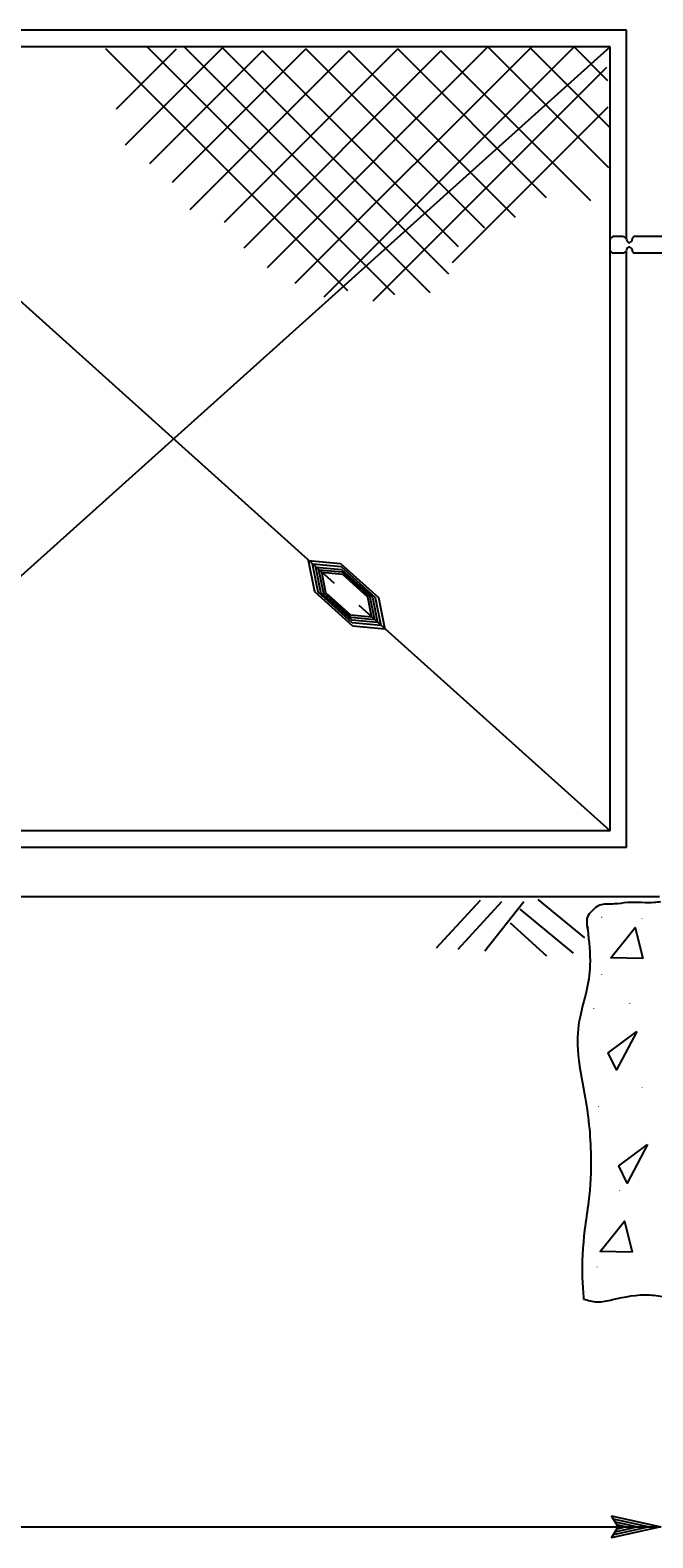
# Model space of a CAD drawing. Extents: x 6710407 to 6714861, y 1868090 to 1871317.
# Drawn here: x 6712744.1 to 6712819.5, y 1870292.1 to 1870474.8 of the extents above; entities that cross this region are included whole.
import ezdxf

# ---------------------------------------------------------------- set-up
doc = ezdxf.new("R2010")
doc.units = 0
for name, color, linetype in [('G-MARK', 7, 'Continuous'), ('G-TEXT', 7, 'Continuous'), ('Nongeo Data(60)', 7, 'Continuous')]:
    doc.layers.add(name, color=color, linetype=linetype)

msp = doc.modelspace()

# ---------------------------------------------------------------- linework, layer by layer
at = {"layer": 'G-MARK'}
msp.add_line((6712595.38, 1870293.46), (6712820.47, 1870293.46), dxfattribs=at)
at = {"layer": 'G-TEXT'}
for p, q in [((6712815.27, 1870293.46), (6712814.47, 1870294.8)), ((6712814.47, 1870294.8), (6712814.47, 1870294.8)), ((6712814.47, 1870294.8), (6712820.47, 1870293.46)), ((6712820.47, 1870293.46), (6712814.47, 1870292.13)), ((6712814.47, 1870292.13), (6712815.27, 1870293.46)), ((6712814.69, 1870294.44), (6712819.09, 1870293.46)), ((6712819.08, 1870293.45), (6712814.71, 1870292.49)), ((6712817.71, 1870293.46), (6712814.88, 1870292.83)), ((6712814.92, 1870294.08), (6712817.71, 1870293.46)), ((6712815.1, 1870293.74), (6712816.33, 1870293.46)), ((6712816.33, 1870293.46), (6712815.12, 1870293.19)), ((6712814.47, 1870292.13), (6712814.47, 1870292.13))]:
    msp.add_line(p, q, dxfattribs=at)
at = {"layer": 'Nongeo Data(60)'}
for p, q in [((6712816.3, 1870474.76), (6712599.3, 1870474.76)), ((6712816.3, 1870449.43), (6712816.3, 1870474.76)), ((6712814.3, 1870472.76), (6712601.3, 1870472.76)), ((6712708.55, 1870472.76), (6712780.87, 1870407.79)), ((6712814.3, 1870472.76), (6712740.11, 1870406.12)), ((6712782.54, 1870443.18), (6712753.23, 1870472.49)), ((6712754.53, 1870465.25), (6712761.77, 1870472.49)), ((6712755.6, 1870460.86), (6712767.47, 1870472.73)), ((6712788.23, 1870442.71), (6712758.21, 1870472.73)), ((6712761.29, 1870456.35), (6712777.43, 1870472.49)), ((6712792.5, 1870442.94), (6712762.72, 1870472.73)), ((6712794.76, 1870445.2), (6712767.23, 1870472.73)), ((6712767.58, 1870451.49), (6712788.59, 1870472.49)), ((6712772.81, 1870446.03), (6712799.51, 1870472.73)), ((6712776.14, 1870444.1), (6712804.89, 1870472.84)), ((6712799.15, 1870450.78), (6712777.43, 1870472.49)), ((6712779.69, 1870442.47), (6712809.95, 1870472.73)), ((6712806.62, 1870454.45), (6712788.59, 1870472.49)), ((6712814.16, 1870458.07), (6712799.51, 1870472.73)), ((6712814.3, 1870462.92), (6712804.73, 1870472.49)), ((6712814.05, 1870468.63), (6712809.95, 1870472.73)), ((6712814.3, 1870449.79), (6712814.3, 1870472.76)), ((6712758.57, 1870458.61), (6712772.21, 1870472.25)), ((6712763.43, 1870453.03), (6712782.65, 1870472.25)), ((6712769.96, 1870448.4), (6712793.81, 1870472.25)), ((6712795.95, 1870448.52), (6712772.21, 1870472.25)), ((6712802.83, 1870452.08), (6712782.65, 1870472.25)), ((6712811.97, 1870454.1), (6712793.81, 1870472.25)), ((6712785.62, 1870441.99), (6712813.9, 1870470.27)), ((6712795.23, 1870446.62), (6712814.09, 1870465.48)), ((6712814.3, 1870377.76), (6712814.3, 1870449.79)), ((6712815.86, 1870449.76), (6712814.72, 1870449.76)), ((6712826, 1870449.76), (6712817.22, 1870449.76)), ((6712815.86, 1870447.76), (6712814.72, 1870447.76)), ((6712816.3, 1870375.76), (6712816.3, 1870448.07)), ((6712826, 1870447.76), (6712817.26, 1870447.76)), ((6712778.55, 1870406.73), (6712777.79, 1870410.52)), ((6712777.79, 1870410.52), (6712781.64, 1870410.16)), ((6712778.93, 1870406.69), (6712778.25, 1870410.1)), ((6712778.25, 1870410.1), (6712781.72, 1870409.78)), ((6712779.28, 1870406.66), (6712778.66, 1870409.73)), ((6712778.66, 1870409.73), (6712781.78, 1870409.44)), ((6712779.59, 1870406.63), (6712779.03, 1870409.39)), ((6712779.03, 1870409.39), (6712781.84, 1870409.13)), ((6712779.87, 1870406.6), (6712779.37, 1870409.09)), ((6712779.37, 1870409.09), (6712781.89, 1870408.85)), ((6712781.64, 1870410.16), (6712786.25, 1870406.02)), ((6712781.72, 1870409.78), (6712785.86, 1870406.05)), ((6712781.78, 1870409.44), (6712785.51, 1870406.08)), ((6712781.84, 1870409.13), (6712785.2, 1870406.11)), ((6712781.89, 1870408.85), (6712784.92, 1870406.13)), ((6712783.16, 1870402.58), (6712778.55, 1870406.73)), ((6712783.08, 1870402.96), (6712778.93, 1870406.69)), ((6712783.01, 1870403.3), (6712779.28, 1870406.66)), ((6712782.94, 1870403.6), (6712779.59, 1870406.63)), ((6712782.89, 1870403.88), (6712779.87, 1870406.6)), ((6712783.85, 1870405.12), (6712814.3, 1870377.76)), ((6712784.92, 1870406.13), (6712785.41, 1870403.64)), ((6712785.2, 1870406.11), (6712785.75, 1870403.34)), ((6712785.51, 1870406.08), (6712786.13, 1870403.01)), ((6712785.86, 1870406.05), (6712786.54, 1870402.64)), ((6712786.25, 1870406.02), (6712787.01, 1870402.22)), ((6712785.41, 1870403.64), (6712782.89, 1870403.88)), ((6712785.75, 1870403.34), (6712782.94, 1870403.6)), ((6712786.13, 1870403.01), (6712783.01, 1870403.3)), ((6712786.54, 1870402.64), (6712783.08, 1870402.96)), ((6712787.01, 1870402.22), (6712783.16, 1870402.58)), ((6712814.3, 1870377.76), (6712601.3, 1870377.76)), ((6712816.3, 1870375.76), (6712599.3, 1870375.76)), ((6712820.3, 1870369.76), (6712595.3, 1870369.76)), ((6712798.55, 1870369.32), (6712793.25, 1870363.57)), ((6712801.17, 1870369.17), (6712795.88, 1870363.41)), ((6712803.84, 1870369.17), (6712799.14, 1870363.19)), ((6712803.38, 1870368.27), (6712809.82, 1870362.97)), ((6712805.57, 1870369.45), (6712811.21, 1870364.81)), ((6712802.2, 1870366.62), (6712806.6, 1870362.62))]:
    msp.add_line(p, q, dxfattribs=at)
for points in [[(6712818.28, 1870362.29), (6712814.38, 1870362.4), (6712817.33, 1870366.06)], [(6712817.56, 1870353.48), (6712815.09, 1870348.83), (6712814.06, 1870350.9)], [(6712818.84, 1870339.76), (6712816.37, 1870335.11), (6712815.35, 1870337.19)], [(6712816.99, 1870326.72), (6712813.09, 1870326.83), (6712816.05, 1870330.49)]]:
    msp.add_lwpolyline(points, close=True, dxfattribs=at)
for centre, radius, start, end in [((6712814.74, 1870449.31), 0.45, 90.9719, 166.9649), ((6712815.86, 1870449.31), 0.45, 13.0351, 89.0281), ((6712816.66, 1870449.4), 0.368, 177.9728, 273.0727), ((6712816.47, 1870449.54), 0.552, 292.64, 356.8611), ((6712817.24, 1870449.54), 0.223, 82.9178, 185.5923), ((6712814.73, 1870448.21), 0.45, 193.0351, 269.0281), ((6712815.86, 1870448.21), 0.45, 270.9719, 346.9649), ((6712816.66, 1870448.12), 0.368, 86.9273, 182.0272), ((6712816.47, 1870447.98), 0.552, 3.1389, 67.36), ((6712817.24, 1870447.99), 0.223, 174.4077, 277.0822)]:
    msp.add_arc(centre, radius, start, end, dxfattribs=at)
for points in [[(6712811.59, 1870365.8), (6712811.51, 1870366.85), (6712811.6, 1870367.37), (6712812.13, 1870368.07), (6712812.56, 1870368.51), (6712813.26, 1870368.86), (6712814.84, 1870368.95), (6712816.41, 1870369.12), (6712818.16, 1870369.12), (6712819.65, 1870369.12), (6712820.44, 1870369.21)], [(6712811.55, 1870366.24), (6712811.59, 1870365.8), (6712811.87, 1870361.5), (6712811.4, 1870358.22), (6712810.66, 1870355.23), (6712810.38, 1870351.3), (6712811.22, 1870345.88), (6712811.97, 1870338.39), (6712811.69, 1870332.87), (6712811.22, 1870329.41), (6712810.94, 1870323.52), (6712811.1, 1870321.06)], [(6712811.1, 1870321.06), (6712812.71, 1870320.71), (6712814.59, 1870320.99), (6712819.08, 1870321.55), (6712821.23, 1870321.27), (6712823.66, 1870320.9), (6712826.28, 1870320.71), (6712829.18, 1870320.62), (6712831.89, 1870320.71), (6712833.48, 1870320.9), (6712834.1, 1870321.06)]]:
    msp.add_spline(points, degree=3, dxfattribs=at)

# ---------------------------------------------------------------- texts
for p in [(6712813.23, 1870367.47), (6712818.12, 1870367.33), (6712813.23, 1870360.54), (6712812.26, 1870356.38), (6712816.63, 1870357.01), (6712818.12, 1870346.82), (6712812.83, 1870344.52), (6712815.4, 1870334.33), (6712812.69, 1870325.09)]:
    msp.add_text('.', height=0.8, rotation=266.9315, dxfattribs=at).set_placement(p)

doc.saveas('drawing.dxf')
